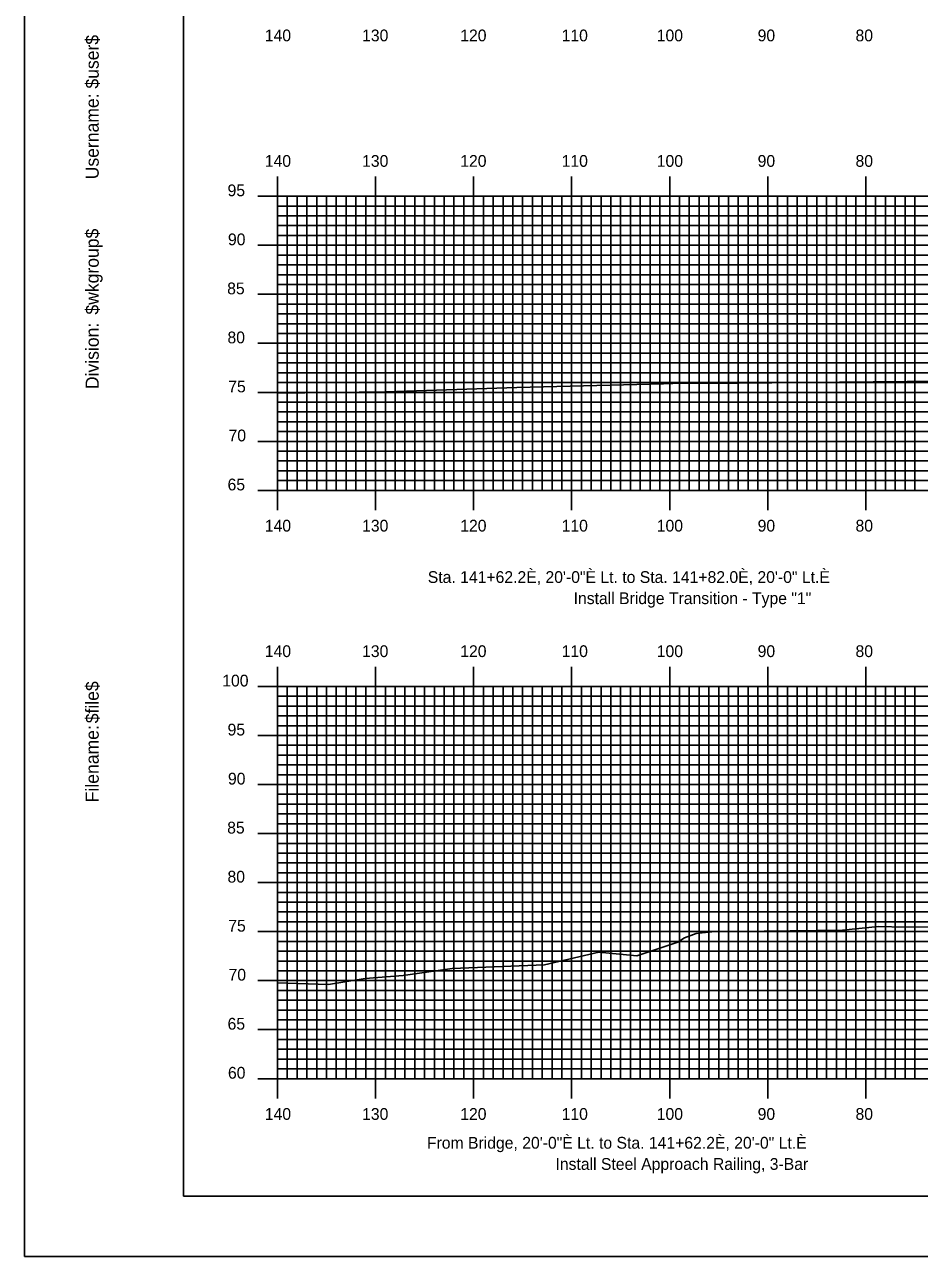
# Model space of a CAD drawing. Extents: x 1776744 to 1777088, y 442591 to 442811.
# Drawn here: x 1776744.5 to 1776835.7, y 442590.5 to 442716.2 of the extents above; entities that cross this region are included whole.
import ezdxf

# ---------------------------------------------------------------- set-up
doc = ezdxf.new("R2010")
doc.units = 0
for name, color, linetype in [('ANNOTATION', 7, 'Continuous'), ('BORDER', 7, 'Continuous'), ('H_V ANNOTATION', 7, 'Continuous'), ('MAJOR', 7, 'Continuous'), ('MINOR', 7, 'Continuous'), ('PLOT BOUNDARY', 7, 'Continuous'), ('S_Roadway_Centerline', 7, 'Continuous')]:
    doc.layers.add(name, color=color, linetype=linetype)

msp = doc.modelspace()

# ---------------------------------------------------------------- linework, layer by layer
at = {"layer": 'BORDER'}
msp.add_lwpolyline([(1776760.65, 442596.67), (1777080.65, 442596.67), (1777080.65, 442806.67), (1776760.65, 442806.67)], close=True, dxfattribs=at)
at = {"layer": 'MAJOR'}
for p, q in [((1776770.25, 442700.67), (1776770.25, 442698.67)), ((1776780.25, 442700.67), (1776780.25, 442698.67)), ((1776790.25, 442700.67), (1776790.25, 442698.67)), ((1776800.25, 442700.67), (1776800.25, 442698.67)), ((1776810.25, 442700.67), (1776810.25, 442698.67)), ((1776820.25, 442700.67), (1776820.25, 442698.67)), ((1776830.25, 442700.67), (1776830.25, 442698.67)), ((1776768.25, 442698.67), (1776770.25, 442698.67)), ((1776770.25, 442698.67), (1777050.25, 442698.67)), ((1776770.25, 442668.67), (1776770.25, 442698.67)), ((1776770.25, 442668.67), (1776770.25, 442698.67)), ((1776770.25, 442698.67), (1777050.25, 442698.67)), ((1776780.25, 442668.67), (1776780.25, 442698.67)), ((1776790.25, 442668.67), (1776790.25, 442698.67)), ((1776800.25, 442668.67), (1776800.25, 442698.67)), ((1776810.25, 442668.67), (1776810.25, 442698.67)), ((1776820.25, 442668.67), (1776820.25, 442698.67)), ((1776830.25, 442668.67), (1776830.25, 442698.67)), ((1776768.25, 442693.67), (1776770.25, 442693.67)), ((1776770.25, 442693.67), (1777050.25, 442693.67)), ((1776768.25, 442688.67), (1776770.25, 442688.67)), ((1776770.25, 442688.67), (1777050.25, 442688.67)), ((1776768.25, 442683.67), (1776770.25, 442683.67)), ((1776770.25, 442683.67), (1777050.25, 442683.67)), ((1776768.25, 442678.67), (1776770.25, 442678.67)), ((1776770.25, 442678.67), (1777050.25, 442678.67)), ((1776768.25, 442673.67), (1776770.25, 442673.67)), ((1776770.25, 442673.67), (1777050.25, 442673.67)), ((1776768.25, 442668.67), (1776770.25, 442668.67)), ((1776770.25, 442668.67), (1777050.25, 442668.67)), ((1776770.25, 442668.67), (1777050.25, 442668.67)), ((1776770.25, 442666.66), (1776770.25, 442668.67)), ((1776780.25, 442666.66), (1776780.25, 442668.67)), ((1776790.25, 442666.66), (1776790.25, 442668.67)), ((1776800.25, 442666.66), (1776800.25, 442668.67)), ((1776810.25, 442666.66), (1776810.25, 442668.67)), ((1776820.25, 442666.66), (1776820.25, 442668.67)), ((1776830.25, 442666.66), (1776830.25, 442668.67)), ((1776770.25, 442650.67), (1776770.25, 442648.67)), ((1776780.25, 442650.67), (1776780.25, 442648.67)), ((1776790.25, 442650.67), (1776790.25, 442648.67)), ((1776800.25, 442650.67), (1776800.25, 442648.67)), ((1776810.25, 442650.67), (1776810.25, 442648.67)), ((1776820.25, 442650.67), (1776820.25, 442648.67)), ((1776830.25, 442650.67), (1776830.25, 442648.67)), ((1776768.25, 442648.67), (1776770.25, 442648.67)), ((1776770.25, 442648.67), (1777050.25, 442648.67)), ((1776770.25, 442608.67), (1776770.25, 442648.67)), ((1776770.25, 442608.67), (1776770.25, 442648.67)), ((1776770.25, 442648.67), (1777050.25, 442648.67)), ((1776780.25, 442608.67), (1776780.25, 442648.67)), ((1776790.25, 442608.67), (1776790.25, 442648.67)), ((1776800.25, 442608.67), (1776800.25, 442648.67)), ((1776810.25, 442608.67), (1776810.25, 442648.67)), ((1776820.25, 442608.67), (1776820.25, 442648.67)), ((1776830.25, 442608.67), (1776830.25, 442648.67)), ((1776768.25, 442643.67), (1776770.25, 442643.67)), ((1776770.25, 442643.67), (1777050.25, 442643.67)), ((1776768.25, 442638.67), (1776770.25, 442638.67)), ((1776770.25, 442638.67), (1777050.25, 442638.67)), ((1776768.25, 442633.67), (1776770.25, 442633.67)), ((1776770.25, 442633.67), (1777050.25, 442633.67)), ((1776768.25, 442628.67), (1776770.25, 442628.67)), ((1776770.25, 442628.67), (1777050.25, 442628.67)), ((1776768.25, 442623.67), (1776770.25, 442623.67)), ((1776770.25, 442623.67), (1777050.25, 442623.67)), ((1776768.25, 442618.67), (1776770.25, 442618.67)), ((1776770.25, 442618.67), (1777050.25, 442618.67)), ((1776768.25, 442613.67), (1776770.25, 442613.67)), ((1776770.25, 442613.67), (1777050.25, 442613.67)), ((1776768.25, 442608.67), (1776770.25, 442608.67)), ((1776770.25, 442608.67), (1777050.25, 442608.67)), ((1776770.25, 442608.67), (1777050.25, 442608.67)), ((1776770.25, 442606.66), (1776770.25, 442608.67)), ((1776780.25, 442606.66), (1776780.25, 442608.67)), ((1776790.25, 442606.66), (1776790.25, 442608.67)), ((1776800.25, 442606.66), (1776800.25, 442608.67)), ((1776810.25, 442606.66), (1776810.25, 442608.67)), ((1776820.25, 442606.66), (1776820.25, 442608.67)), ((1776830.25, 442606.66), (1776830.25, 442608.67))]:
    msp.add_line(p, q, dxfattribs=at)
at = {"layer": 'MINOR'}
for p, q in [((1776771.25, 442668.67), (1776771.25, 442698.67)), ((1776772.25, 442668.67), (1776772.25, 442698.67)), ((1776773.25, 442668.67), (1776773.25, 442698.67)), ((1776774.25, 442668.67), (1776774.25, 442698.67)), ((1776775.25, 442668.67), (1776775.25, 442698.67)), ((1776776.25, 442668.67), (1776776.25, 442698.67)), ((1776777.25, 442668.67), (1776777.25, 442698.67)), ((1776778.25, 442668.67), (1776778.25, 442698.67)), ((1776779.25, 442668.67), (1776779.25, 442698.67)), ((1776781.25, 442668.67), (1776781.25, 442698.67)), ((1776782.25, 442668.67), (1776782.25, 442698.67)), ((1776783.25, 442668.67), (1776783.25, 442698.67)), ((1776784.25, 442668.67), (1776784.25, 442698.67)), ((1776785.25, 442668.67), (1776785.25, 442698.67)), ((1776786.25, 442668.67), (1776786.25, 442698.67)), ((1776787.25, 442668.67), (1776787.25, 442698.67)), ((1776788.25, 442668.67), (1776788.25, 442698.67)), ((1776789.25, 442668.67), (1776789.25, 442698.67)), ((1776791.25, 442668.67), (1776791.25, 442698.67)), ((1776792.25, 442668.67), (1776792.25, 442698.67)), ((1776793.25, 442668.67), (1776793.25, 442698.67)), ((1776794.25, 442668.67), (1776794.25, 442698.67)), ((1776795.25, 442668.67), (1776795.25, 442698.67)), ((1776796.25, 442668.67), (1776796.25, 442698.67)), ((1776797.25, 442668.67), (1776797.25, 442698.67)), ((1776798.25, 442668.67), (1776798.25, 442698.67)), ((1776799.25, 442668.67), (1776799.25, 442698.67)), ((1776801.25, 442668.67), (1776801.25, 442698.67)), ((1776802.25, 442668.67), (1776802.25, 442698.67)), ((1776803.25, 442668.67), (1776803.25, 442698.67)), ((1776804.25, 442668.67), (1776804.25, 442698.67)), ((1776805.25, 442668.67), (1776805.25, 442698.67)), ((1776806.25, 442668.67), (1776806.25, 442698.67)), ((1776807.25, 442668.67), (1776807.25, 442698.67)), ((1776808.25, 442668.67), (1776808.25, 442698.67)), ((1776809.25, 442668.67), (1776809.25, 442698.67)), ((1776811.25, 442668.67), (1776811.25, 442698.67)), ((1776812.25, 442668.67), (1776812.25, 442698.67)), ((1776813.25, 442668.67), (1776813.25, 442698.67)), ((1776814.25, 442668.67), (1776814.25, 442698.67)), ((1776815.25, 442668.67), (1776815.25, 442698.67)), ((1776816.25, 442668.67), (1776816.25, 442698.67)), ((1776817.25, 442668.67), (1776817.25, 442698.67)), ((1776818.25, 442668.67), (1776818.25, 442698.67)), ((1776819.25, 442668.67), (1776819.25, 442698.67)), ((1776821.25, 442668.67), (1776821.25, 442698.67)), ((1776822.25, 442668.67), (1776822.25, 442698.67)), ((1776823.25, 442668.67), (1776823.25, 442698.67)), ((1776824.25, 442668.67), (1776824.25, 442698.67)), ((1776825.25, 442668.67), (1776825.25, 442698.67)), ((1776826.25, 442668.67), (1776826.25, 442698.67)), ((1776827.25, 442668.67), (1776827.25, 442698.67)), ((1776828.25, 442668.67), (1776828.25, 442698.67)), ((1776829.25, 442668.67), (1776829.25, 442698.67)), ((1776831.25, 442668.67), (1776831.25, 442698.67)), ((1776832.25, 442668.67), (1776832.25, 442698.67)), ((1776833.25, 442668.67), (1776833.25, 442698.67)), ((1776834.25, 442668.67), (1776834.25, 442698.67)), ((1776835.25, 442668.67), (1776835.25, 442698.67)), ((1776770.25, 442697.67), (1777050.25, 442697.67)), ((1776770.25, 442697.67), (1776772.25, 442697.67)), ((1776770.25, 442696.67), (1777050.25, 442696.67)), ((1776770.25, 442696.67), (1776772.25, 442696.67)), ((1776770.25, 442695.67), (1777050.25, 442695.67)), ((1776770.25, 442695.67), (1776772.25, 442695.67)), ((1776770.25, 442694.67), (1777050.25, 442694.67)), ((1776770.25, 442694.67), (1776772.25, 442694.67)), ((1776770.25, 442692.67), (1777050.25, 442692.67)), ((1776770.25, 442692.67), (1776772.25, 442692.67)), ((1776770.25, 442691.67), (1777050.25, 442691.67)), ((1776770.25, 442691.67), (1776772.25, 442691.67)), ((1776770.25, 442690.67), (1777050.25, 442690.67)), ((1776770.25, 442690.67), (1776772.25, 442690.67)), ((1776770.25, 442689.67), (1777050.25, 442689.67)), ((1776770.25, 442689.67), (1776772.25, 442689.67)), ((1776770.25, 442687.67), (1777050.25, 442687.67)), ((1776770.25, 442687.67), (1776772.25, 442687.67)), ((1776770.25, 442686.67), (1777050.25, 442686.67)), ((1776770.25, 442686.67), (1776772.25, 442686.67)), ((1776770.25, 442685.67), (1777050.25, 442685.67)), ((1776770.25, 442685.67), (1776772.25, 442685.67)), ((1776770.25, 442684.67), (1777050.25, 442684.67)), ((1776770.25, 442684.67), (1776772.25, 442684.67)), ((1776770.25, 442682.67), (1777050.25, 442682.67)), ((1776770.25, 442682.67), (1776772.25, 442682.67)), ((1776770.25, 442681.67), (1777050.25, 442681.67)), ((1776770.25, 442681.67), (1776772.25, 442681.67)), ((1776770.25, 442680.67), (1777050.25, 442680.67)), ((1776770.25, 442680.67), (1776772.25, 442680.67)), ((1776770.25, 442679.67), (1777050.25, 442679.67)), ((1776770.25, 442679.67), (1776772.25, 442679.67)), ((1776770.25, 442677.67), (1777050.25, 442677.67)), ((1776770.25, 442677.67), (1776772.25, 442677.67)), ((1776770.25, 442676.67), (1777050.25, 442676.67)), ((1776770.25, 442676.67), (1776772.25, 442676.67)), ((1776770.25, 442675.67), (1777050.25, 442675.67)), ((1776770.25, 442675.67), (1776772.25, 442675.67)), ((1776770.25, 442674.67), (1777050.25, 442674.67)), ((1776770.25, 442674.67), (1776772.25, 442674.67)), ((1776770.25, 442672.67), (1777050.25, 442672.67)), ((1776770.25, 442672.67), (1776772.25, 442672.67)), ((1776770.25, 442671.67), (1777050.25, 442671.67)), ((1776770.25, 442671.67), (1776772.25, 442671.67)), ((1776770.25, 442670.67), (1777050.25, 442670.67)), ((1776770.25, 442670.67), (1776772.25, 442670.67)), ((1776770.25, 442669.67), (1777050.25, 442669.67)), ((1776770.25, 442669.67), (1776772.25, 442669.67)), ((1776771.25, 442608.67), (1776771.25, 442648.67)), ((1776772.25, 442608.67), (1776772.25, 442648.67)), ((1776773.25, 442608.67), (1776773.25, 442648.67)), ((1776774.25, 442608.67), (1776774.25, 442648.67)), ((1776775.25, 442608.67), (1776775.25, 442648.67)), ((1776776.25, 442608.67), (1776776.25, 442648.67)), ((1776777.25, 442608.67), (1776777.25, 442648.67)), ((1776778.25, 442608.67), (1776778.25, 442648.67)), ((1776779.25, 442608.67), (1776779.25, 442648.67)), ((1776781.25, 442608.67), (1776781.25, 442648.67)), ((1776782.25, 442608.67), (1776782.25, 442648.67)), ((1776783.25, 442608.67), (1776783.25, 442648.67)), ((1776784.25, 442608.67), (1776784.25, 442648.67)), ((1776785.25, 442608.67), (1776785.25, 442648.67)), ((1776786.25, 442608.67), (1776786.25, 442648.67)), ((1776787.25, 442608.67), (1776787.25, 442648.67)), ((1776788.25, 442608.67), (1776788.25, 442648.67)), ((1776789.25, 442608.67), (1776789.25, 442648.67)), ((1776791.25, 442608.67), (1776791.25, 442648.67)), ((1776792.25, 442608.67), (1776792.25, 442648.67)), ((1776793.25, 442608.67), (1776793.25, 442648.67)), ((1776794.25, 442608.67), (1776794.25, 442648.67)), ((1776795.25, 442608.67), (1776795.25, 442648.67)), ((1776796.25, 442608.67), (1776796.25, 442648.67)), ((1776797.25, 442608.67), (1776797.25, 442648.67)), ((1776798.25, 442608.67), (1776798.25, 442648.67)), ((1776799.25, 442608.67), (1776799.25, 442648.67)), ((1776801.25, 442608.67), (1776801.25, 442648.67)), ((1776802.25, 442608.67), (1776802.25, 442648.67)), ((1776803.25, 442608.67), (1776803.25, 442648.67)), ((1776804.25, 442608.67), (1776804.25, 442648.67)), ((1776805.25, 442608.67), (1776805.25, 442648.67)), ((1776806.25, 442608.67), (1776806.25, 442648.67)), ((1776807.25, 442608.67), (1776807.25, 442648.67)), ((1776808.25, 442608.67), (1776808.25, 442648.67)), ((1776809.25, 442608.67), (1776809.25, 442648.67)), ((1776811.25, 442608.67), (1776811.25, 442648.67)), ((1776812.25, 442608.67), (1776812.25, 442648.67)), ((1776813.25, 442608.67), (1776813.25, 442648.67)), ((1776814.25, 442608.67), (1776814.25, 442648.67)), ((1776815.25, 442608.67), (1776815.25, 442648.67)), ((1776816.25, 442608.67), (1776816.25, 442648.67)), ((1776817.25, 442608.67), (1776817.25, 442648.67)), ((1776818.25, 442608.67), (1776818.25, 442648.67)), ((1776819.25, 442608.67), (1776819.25, 442648.67)), ((1776821.25, 442608.67), (1776821.25, 442648.67)), ((1776822.25, 442608.67), (1776822.25, 442648.67)), ((1776823.25, 442608.67), (1776823.25, 442648.67)), ((1776824.25, 442608.67), (1776824.25, 442648.67)), ((1776825.25, 442608.67), (1776825.25, 442648.67)), ((1776826.25, 442608.67), (1776826.25, 442648.67)), ((1776827.25, 442608.67), (1776827.25, 442648.67)), ((1776828.25, 442608.67), (1776828.25, 442648.67)), ((1776829.25, 442608.67), (1776829.25, 442648.67)), ((1776831.25, 442608.67), (1776831.25, 442648.67)), ((1776832.25, 442608.67), (1776832.25, 442648.67)), ((1776833.25, 442608.67), (1776833.25, 442648.67)), ((1776834.25, 442608.67), (1776834.25, 442648.67)), ((1776835.25, 442608.67), (1776835.25, 442648.67)), ((1776770.25, 442647.67), (1777050.25, 442647.67)), ((1776770.25, 442647.67), (1776772.25, 442647.67)), ((1776770.25, 442646.67), (1777050.25, 442646.67)), ((1776770.25, 442646.67), (1776772.25, 442646.67)), ((1776770.25, 442645.67), (1777050.25, 442645.67)), ((1776770.25, 442645.67), (1776772.25, 442645.67)), ((1776770.25, 442644.67), (1777050.25, 442644.67)), ((1776770.25, 442644.67), (1776772.25, 442644.67)), ((1776770.25, 442642.67), (1777050.25, 442642.67)), ((1776770.25, 442642.67), (1776772.25, 442642.67)), ((1776770.25, 442641.67), (1777050.25, 442641.67)), ((1776770.25, 442641.67), (1776772.25, 442641.67)), ((1776770.25, 442640.67), (1777050.25, 442640.67)), ((1776770.25, 442640.67), (1776772.25, 442640.67)), ((1776770.25, 442639.67), (1777050.25, 442639.67)), ((1776770.25, 442639.67), (1776772.25, 442639.67)), ((1776770.25, 442637.67), (1777050.25, 442637.67)), ((1776770.25, 442637.67), (1776772.25, 442637.67)), ((1776770.25, 442636.67), (1777050.25, 442636.67)), ((1776770.25, 442636.67), (1776772.25, 442636.67)), ((1776770.25, 442635.67), (1777050.25, 442635.67)), ((1776770.25, 442635.67), (1776772.25, 442635.67)), ((1776770.25, 442634.67), (1777050.25, 442634.67)), ((1776770.25, 442634.67), (1776772.25, 442634.67)), ((1776770.25, 442632.67), (1777050.25, 442632.67)), ((1776770.25, 442632.67), (1776772.25, 442632.67)), ((1776770.25, 442631.67), (1777050.25, 442631.67)), ((1776770.25, 442631.67), (1776772.25, 442631.67)), ((1776770.25, 442630.67), (1777050.25, 442630.67)), ((1776770.25, 442630.67), (1776772.25, 442630.67)), ((1776770.25, 442629.67), (1777050.25, 442629.67)), ((1776770.25, 442629.67), (1776772.25, 442629.67)), ((1776770.25, 442627.67), (1777050.25, 442627.67)), ((1776770.25, 442627.67), (1776772.25, 442627.67)), ((1776770.25, 442626.67), (1777050.25, 442626.67)), ((1776770.25, 442626.67), (1776772.25, 442626.67)), ((1776770.25, 442625.67), (1777050.25, 442625.67)), ((1776770.25, 442625.67), (1776772.25, 442625.67)), ((1776770.25, 442624.67), (1777050.25, 442624.67)), ((1776770.25, 442624.67), (1776772.25, 442624.67)), ((1776770.25, 442622.67), (1777050.25, 442622.67)), ((1776770.25, 442622.67), (1776772.25, 442622.67)), ((1776770.25, 442621.67), (1777050.25, 442621.67)), ((1776770.25, 442621.67), (1776772.25, 442621.67)), ((1776770.25, 442620.67), (1777050.25, 442620.67)), ((1776770.25, 442620.67), (1776772.25, 442620.67)), ((1776770.25, 442619.67), (1777050.25, 442619.67)), ((1776770.25, 442619.67), (1776772.25, 442619.67)), ((1776770.25, 442617.67), (1777050.25, 442617.67)), ((1776770.25, 442617.67), (1776772.25, 442617.67)), ((1776770.25, 442616.67), (1777050.25, 442616.67)), ((1776770.25, 442616.67), (1776772.25, 442616.67)), ((1776770.25, 442615.67), (1777050.25, 442615.67)), ((1776770.25, 442615.67), (1776772.25, 442615.67)), ((1776770.25, 442614.67), (1777050.25, 442614.67)), ((1776770.25, 442614.67), (1776772.25, 442614.67)), ((1776770.25, 442612.67), (1777050.25, 442612.67)), ((1776770.25, 442612.67), (1776772.25, 442612.67)), ((1776770.25, 442611.67), (1777050.25, 442611.67)), ((1776770.25, 442611.67), (1776772.25, 442611.67)), ((1776770.25, 442610.67), (1777050.25, 442610.67)), ((1776770.25, 442610.67), (1776772.25, 442610.67)), ((1776770.25, 442609.67), (1777050.25, 442609.67)), ((1776770.25, 442609.67), (1776772.25, 442609.67))]:
    msp.add_line(p, q, dxfattribs=at)
at = {"layer": 'PLOT BOUNDARY'}
msp.add_lwpolyline([(1776744.46, 442590.55), (1777084.46, 442590.55), (1777084.46, 442810.55), (1776744.46, 442810.55)], close=True, dxfattribs=at)
at = {"layer": 'S_Roadway_Centerline'}
for points in [[(1776770.25, 442678.58), (1776781.38, 442678.73), (1776781.38, 442678.73), (1776781.38, 442678.73), (1776794.65, 442679.18), (1776809.63, 442679.55), (1776811.52, 442679.59), (1776817.22, 442679.61), (1776837.9, 442679.81), (1776845.72, 442679.63), (1776854.19, 442679.32), (1776862.47, 442679.32), (1776878.45, 442679.61), (1776883.99, 442679.59), (1776901, 442680.19), (1776903.57, 442680.32), (1776905.98, 442680.4), (1776915.32, 442680.59), (1776925.35, 442680.95), (1776928.99, 442681.08), (1776948.02, 442681.71), (1776952.13, 442681.88), (1776973.31, 442683.01)], [(1776770.25, 442618.44), (1776775.46, 442618.26), (1776779.2, 442618.88), (1776783.08, 442619.2), (1776788.05, 442619.9), (1776797.49, 442620.29), (1776803.01, 442621.56), (1776806.89, 442621.2), (1776811.09, 442622.58), (1776811.75, 442623.02), (1776812.96, 442623.48), (1776814.2, 442623.62), (1776814.54, 442623.64), (1776827.89, 442623.82), (1776831.53, 442624.2), (1776834.24, 442624.13), (1776857.61, 442624.44)]]:
    msp.add_lwpolyline(points, dxfattribs=at)

# ---------------------------------------------------------------- texts
at = {"layer": 'ANNOTATION'}
for s, p in [('Sta. 141+62.2È, 20\'-0"È Lt. to Sta. 141+82.0È, 20\'-0" Lt.È', (1776785.58, 442659.23)), ('Install Bridge Transition - Type "1"', (1776800.45, 442657.07)), ('From Bridge, 20\'-0"È Lt. to Sta. 141+62.2È, 20\'-0" Lt.È', (1776785.49, 442601.53)), ('Install Steel Approach Railing, 3-Bar', (1776798.6, 442599.37))]:
    msp.add_text(s, height=1.2, dxfattribs=at).set_placement(p)
at = {"layer": 'BORDER'}
for s, p in [('$user$', (1776752.02, 442709.65)), ('Username:', (1776752.02, 442700.4)), ('$wkgroup$', (1776752.02, 442686.6)), ('Division:', (1776752.02, 442679)), ('$file$', (1776752.02, 442644.92)), ('Filename:', (1776752.02, 442636.86))]:
    msp.add_text(s, height=1.339, rotation=90, dxfattribs=at).set_placement(p)
at = {"layer": 'H_V ANNOTATION'}
for s, p in [('140', (1776768.96, 442714.47)), ('130', (1776778.88, 442714.47)), ('120', (1776788.89, 442714.47)), ('110', (1776799.23, 442714.47)), ('100', (1776808.93, 442714.47)), ('90', (1776819.22, 442714.47)), ('80', (1776829.2, 442714.47)), ('140', (1776768.96, 442701.67)), ('130', (1776778.88, 442701.67)), ('120', (1776788.89, 442701.67)), ('110', (1776799.23, 442701.67)), ('100', (1776808.93, 442701.67)), ('90', (1776819.22, 442701.67)), ('80', (1776829.2, 442701.67)), ('95', (1776765.16, 442698.67)), ('90', (1776765.2, 442693.67)), ('85', (1776765.12, 442688.67)), ('80', (1776765.15, 442683.67)), ('75', (1776765.23, 442678.67)), ('70', (1776765.26, 442673.67)), ('65', (1776765.16, 442668.67)), ('140', (1776768.96, 442664.47)), ('130', (1776778.88, 442664.47)), ('120', (1776788.89, 442664.47)), ('110', (1776799.23, 442664.47)), ('100', (1776808.93, 442664.47)), ('90', (1776819.22, 442664.47)), ('80', (1776829.2, 442664.47)), ('140', (1776768.96, 442651.67)), ('130', (1776778.88, 442651.67)), ('120', (1776788.89, 442651.67)), ('110', (1776799.23, 442651.67)), ('100', (1776808.93, 442651.67)), ('90', (1776819.22, 442651.67)), ('80', (1776829.2, 442651.67)), ('100', (1776764.62, 442648.67)), ('95', (1776765.16, 442643.67)), ('90', (1776765.2, 442638.67)), ('85', (1776765.12, 442633.67)), ('80', (1776765.15, 442628.67)), ('75', (1776765.23, 442623.67)), ('70', (1776765.26, 442618.67)), ('65', (1776765.16, 442613.67)), ('60', (1776765.2, 442608.67)), ('140', (1776768.96, 442604.47)), ('130', (1776778.88, 442604.47)), ('120', (1776788.89, 442604.47)), ('110', (1776799.23, 442604.47)), ('100', (1776808.93, 442604.47)), ('90', (1776819.22, 442604.47)), ('80', (1776829.2, 442604.47))]:
    msp.add_text(s, height=1.2, dxfattribs=at).set_placement(p)
at = {"layer": 'MAJOR'}
for p in [(1776770.24, 442668.67), (1776770.24, 442608.67)]:
    msp.add_text('-', height=0.012, dxfattribs=at).set_placement(p)

doc.saveas('drawing.dxf')
